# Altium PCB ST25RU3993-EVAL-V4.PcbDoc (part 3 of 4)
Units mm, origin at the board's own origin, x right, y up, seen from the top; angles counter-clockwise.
Board outline 76.25 x 96.25 mm, 6 copper layers (Top Layer, RF GND, Power, GND, Routing, Bottom GND), stack 1.022 mm thick; 319 components, 214 nets, 994 pads, 1429 vias.
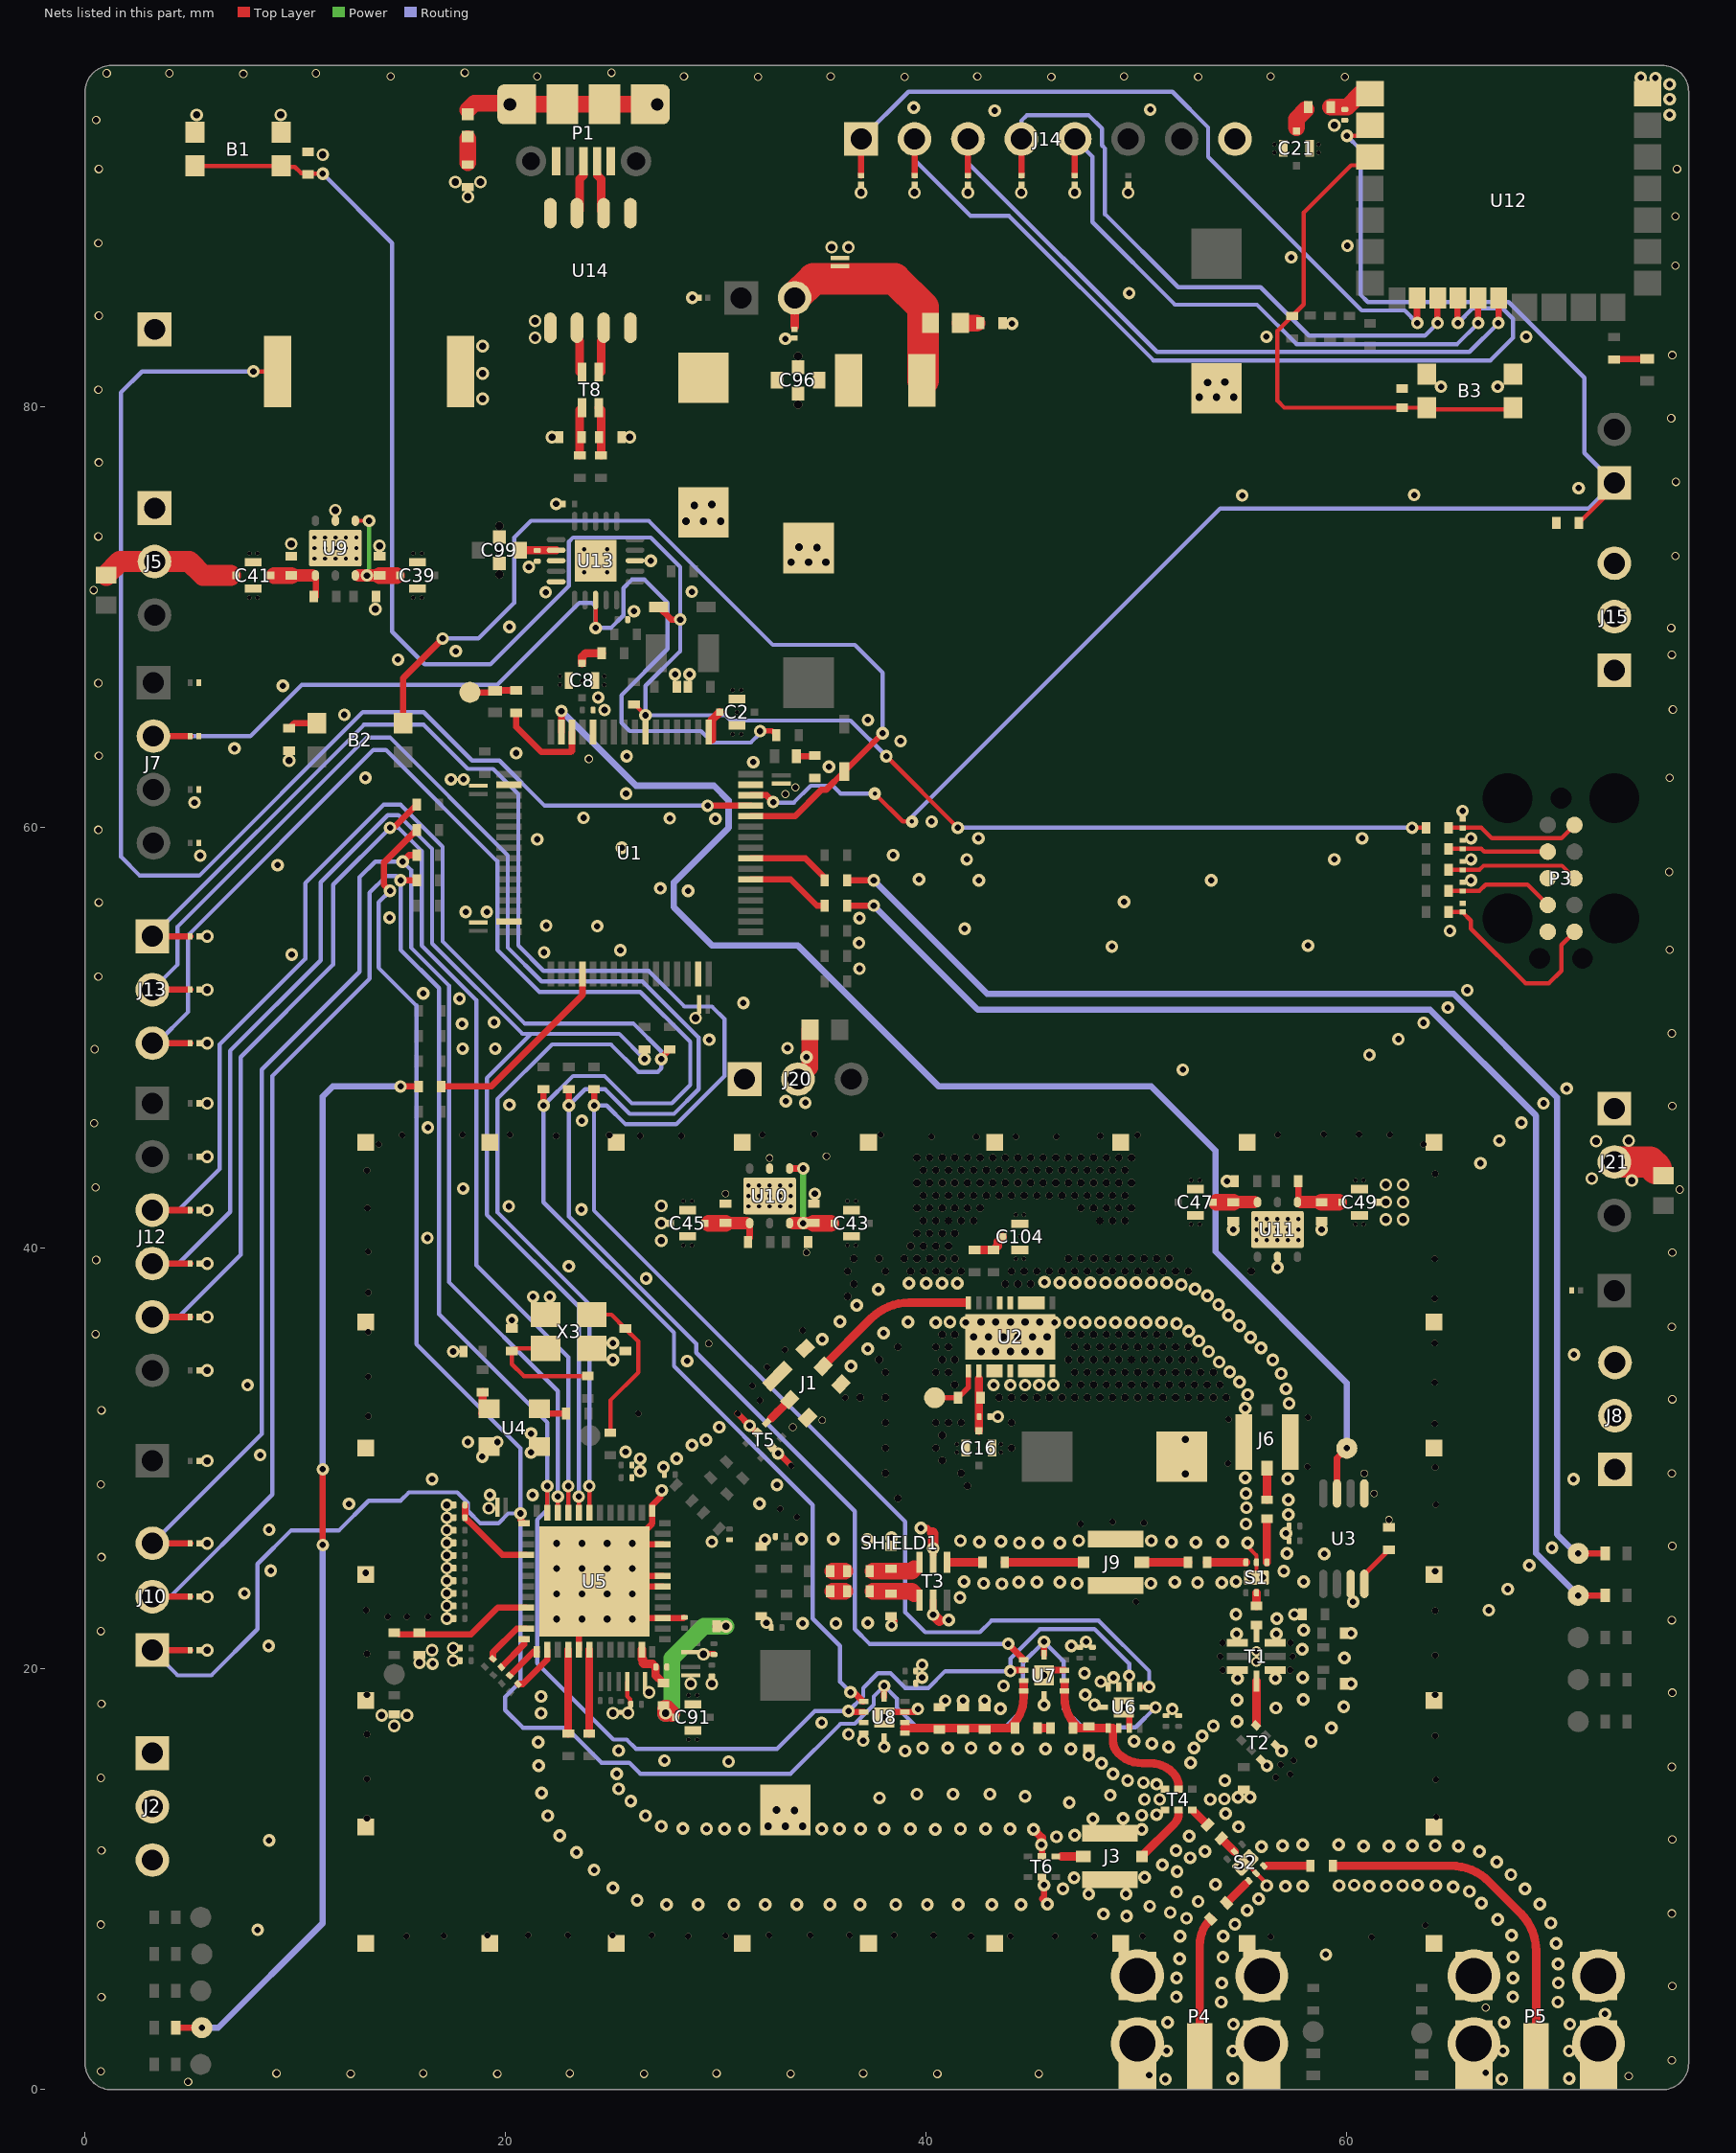
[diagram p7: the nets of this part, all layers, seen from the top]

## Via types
v1: diameter 0.6, hole 0.3, Top Layer to Bottom GND, tented both sides, 407 vias
v2: diameter 0.35, hole 0.35, Top Layer to Bottom GND, tented both sides, 245 vias
v3: diameter 0.61, hole 0.3, Top Layer to Bottom GND, tented both sides, 240 vias
v4: diameter 0.3, hole 0.3, Top Layer to Bottom GND, tented both sides, 105 vias
v5: diameter 0.4, hole 0.3, Top Layer to Bottom GND, tented both sides, 93 vias
v6: diameter 0.6/0.6/0.6/0.6/0.6/0.6 (per signal layer), hole 0.35, Top Layer to Bottom GND, tented both sides, 92 vias
v7: diameter 0.6, hole 0.35, Top Layer to Bottom GND, tented both sides, 71 vias
v8: diameter 0.2, hole 0.2, Top Layer to Bottom GND, tented both sides, 60 vias
v9: diameter 0.4, hole 0.2, Top Layer to Bottom GND, 45 vias
v10: diameter 0.6, hole 0.35, Top Layer to Bottom GND, 16 vias
v11: diameter 0.66, hole 0.33, Top Layer to Bottom GND, tented both sides, 16 vias
v12: diameter 0.35, hole 0.3, Top Layer to Bottom GND, tented both sides, 10 vias
v13: diameter 0.4, hole 0.4, Top Layer to Bottom GND, tented both sides, 6 vias
v14: diameter 1.8/2.51/2.51/2.51/2.51/2.51 (per signal layer), hole 1.71, Top Layer to Bottom GND, 6 vias
v15: diameter 0.5, hole 0.2, Top Layer to Bottom GND, 4 vias
v16: diameter 0.6, hole 0.3, Top Layer to Bottom GND, tented bottom, 4 vias
v17: diameter 0.5, hole 0.3, Top Layer to Bottom GND, tented both sides, 2 vias
v18: diameter 1.8/1.8/1.8/1.8/1.8/2.51 (per signal layer), hole 1.71, Top Layer to Bottom GND, 2 vias
v19: diameter 0.6, hole 0.2, Top Layer to Bottom GND, tented both sides, 2 vias
v20: diameter 0.4, hole 0.2, Top Layer to Bottom GND, tented both sides, 2 vias
v21: diameter 0.8, hole 0.4, Top Layer to Bottom GND, tented both sides, 1 vias

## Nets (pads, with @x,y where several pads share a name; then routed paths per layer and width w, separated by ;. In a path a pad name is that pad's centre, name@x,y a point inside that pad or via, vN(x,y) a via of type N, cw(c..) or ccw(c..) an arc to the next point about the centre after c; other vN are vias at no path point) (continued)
CD2: C59.1 C60.1 U5.40 | length 4.2
  Top Layer w0.3: C59.1@18.07,27.8 18.07,27.2 18.255,27.015 18.262,27.015 18.445,26.832 18.445,26.825 19.845,25.425 U5.40@20.975,25.425
CLK: D22.1 J10.1 R8.1 U5.37 U6.5 U7.5 U8.5 | length 116.3
  Top Layer w0.2: U6.5@50.375,18.175 v1(50.9,18.175)
  Top Layer w0.3: J10.1@3.2,20.9 D22.1@4.994,20.9 ; v1(14.5,57) 14.2,57.3 14.2,58.333 R8.1@15.767,59.9 ; v1(20.7,27.4) 20.7,27.1 U5.37@20.875,26.925 ; U8.5@38,18.675 v1(38,19.2) ; U7.5@45.6,20.675 v1(45.6,21.3)
  Routing w0.2: J10.1@3.2,20.9 4.4,19.7 6,19.7 8.2,21.9 8.2,25 9.8,26.6 12.075,26.6 13.475,28 15,28 15.4,28.4 17.7,28.4 18.2,27.9 18.2,27.525 18.8,26.925 19.65,26.925 20.125,27.4 v1(20.7,27.4) ; J10.1@3.2,21.1 J10.1@3.4,20.9 ; v1(14.5,57) 13.95,56.45 13.95,53.35 15.75,51.55 15.75,35.45 20.7,30.5 v1(20.7,27.4) ; v1(50.9,18.175) 49.95,17.225 47.425,17.225 46.525,18.125 46.525,20.375 v1(45.6,21.3) 44.6,20.3 44.6,18.075 43.75,17.225 39.55,17.225 38.6,18.175 38.6,18.6 v1(38,19.2) 37.5,18.7 37.5,18.3 36.6,17.4 35.925,17.4 33.55,15.025 26.4,15.025 25.875,15.55 24.55,15.55 22.888,17.213 20.812,17.213 19.975,18.05 19.975,18.675 20.7,19.4 v1(20.7,27.4)
COMN_A: C80.1 U5.48 | length 1.8
  Top Layer w0.3: C80.1@19.791,20.091 20.875,21.175 U5.48@20.875,21.425
COMN_B: C82.1 U5.2 | length 2.3
  Top Layer w0.3: C82.1@20.591,19.291 20.816,19.291 21.975,20.45 U5.2@21.975,20.925
COMP_A: C79.1 U5.47 | length 2.4
  Top Layer w0.3: C79.1@19.391,20.491 19.391,20.791 20.525,21.925 U5.47@20.975,21.925
COMP_B: C81.1 U5.1 | length 1.8
  Top Layer w0.3: C81.1@20.191,19.691 21.325,20.825 U5.1@21.475,20.825
CRC_ERR: D13.2 R66.2 TP17.1 | length 53.1
  Top Layer w0.3: D13.2@4.32,2.95 v1(5.55,2.95) ; v1(11.3,25.9) v1(11.3,29.5) ; v1(15,47.7) R66.2@15.867,47.7
  Routing w0.3: v1(5.55,2.95) 6.325,2.95 11.3,7.925 v1(11.3,25.9) ; v1(11.3,29.5) 11.3,47.225 11.775,47.7 v1(15,47.7)
CRC_ERR_LED: R66.1 U1.36 | length 9.5
  Top Layer w0.3: R66.1@16.933,47.7 19.3,47.7 23.65,52.05 U1.36@23.65,53.05
D_CMC_N: C101.1 R41.1 T8.3 | length 2.3
  Top Layer w0.41: T8.3@24.425,79.975 24.53,79.87 R41.1@24.53,77.708
D_CMC_P: C102.1 R47.1 T8.2 | length 2.3
  Top Layer w0.41: R47.1@23.52,77.708 23.52,78.575 23.52,78.825 23.52,79.075 23.52,79.87 T8.2@23.625,79.975
D_CON_N: P1.2 U14.2 | length 2
  Top Layer w0.41: P1.2@24.35,91.05 24.35,91.025 24.53,90.845 24.53,89.355 U14.2@24.66,89.225
D_CON_P: P1.3 U14.3 | length 2
  Top Layer w0.41: U14.3@23.39,89.225 23.52,89.355 23.52,90.845 23.7,91.025 P1.3@23.7,91.05
D_ESD_N: T8.4 U14.7 | length 1.7
  Top Layer w0.41: T8.4@24.53,81.675 24.53,83.145 U14.7@24.66,83.275
D_ESD_P: T8.1 U14.6 | length 1.7
  Top Layer w0.41: U14.6@23.39,83.275 23.52,83.145 T8.1@23.52,81.675
Detector: TP4.1 U1.15 U3.7 | length 66.5
  Top Layer w0.3: U1.15@22.65,64.55 v1(22.65,65.55) ; U3.7@59.529,28.35 59.529,30.029 v1(60,30.5)
  Routing w0.3: v1(22.65,65.55) 26.2,62 29.9,62 30.6,61.3 30.6,60 28,57.4 28,56.222 29.822,54.4 33.9,54.4 40.6,47.7 50.7,47.7 53.75,44.65 53.75,39.85 60,33.6 v1(60,30.5)
DTR: D48.1 J7.2 R37.1 U13.18 | length 48.2
  Top Layer w0.2: v1(24.275,69.5) U13.18@24.275,70.825
  Top Layer w0.25: v1(32.1,64.6) 32.667,64.6 R37.1@32.867,64.4
  Top Layer w0.3: J7.2@3.251,64.36 D48.1@4.994,64.36
  Routing w0.2: J7.2@3.251,64.36 7.86,64.36 10.3,66.8 19.6,66.8 23.5,70.7 24.1,70.7 24.275,70.525 v1(24.275,69.5) 25,69.5 25.6,70.1 25.6,71.4 26,71.8 26.6,71.8 27.7,70.7 27.7,68.5 25.5,66.3 25.5,65 25.9,64.6 29.294,64.6 29.844,64.05 31.65,64.05 32.1,64.5 v1(32.1,64.6)
EN: D35.1 J12.3 R13.1 U5.31 | length 79.7
  Top Layer w0.2: U5.31@23.975,27.425 v1(23.975,28.7)
  Top Layer w0.3: J12.3@3.2,41.82 D35.1@4.994,41.82 ; v1(27.4,49) 27.4,49.067 R13.1@27.8,49.467
  Routing w0.2: J12.3@3.2,41.82 4.44,41.82 6.4,43.78 6.4,49.7 10.475,53.775 10.475,57.375 14.2,61.1 15,61.1 17,59.1 17,54.6 20.9,50.7 26.067,50.7 27.4,49.367 v1(27.4,49) 27.4,48.567 27.233,48.4 26.3,48.4 25,49.7 22.2,49.7 19.6,47.1 19.6,41.725 23.975,37.35 v1(23.975,28.7) v1@23.975,28.5
ETC_1: D25.1 J13.1 R40.2 U6.6 | length 98.8
  Top Layer w0.2: U6.6@50.15,19.15 v1(50.6,19.15)
  Top Layer w0.3: J13.1@3.2,54.84 D25.1@4.994,54.84 ; v1(24.2,46.8) R40.2@24.2,47.567
  Routing w0.2: J13.1@3.2,54.84 13.26,64.9 16.1,64.9 18.2,62.8 19.4,62.8 20.6,61.6 20.6,54.4 21.8,53.2 26.8,53.2 28.5,51.5 29.807,51.5 30.4,50.907 30.4,48.2 28.1,45.9 25.7,45.9 24.8,46.8 v1(24.2,46.8) 24.2,41.8 39,27 39,22.7 39.95,21.75 42.55,21.75 43.1,22.3 48.2,22.3 50.6,19.9 v1(50.6,19.15)
ETC_2: D26.1 J13.2 R39.2 U7.6 | length 92.1
  Top Layer w0.3: J13.2@3.2,52.3 D26.1@4.994,52.3 ; v1(23,46.8) R39.2@23,47.567 ; v1(43.9,21.2) 43.9,21.175 U7.6@44.625,20.45
  Routing w0.2: J13.2@3.2,52.3 4.4,53.5 4.4,55.3 13.4,64.3 14.493,64.3 20.1,58.693 20.1,54.3 21.7,52.7 26.5,52.7 29.175,50.025 29.175,47.575 28,46.4 25.9,46.4 24.725,47.575 23.775,47.575 v1(23,46.8) 23,41.525 29.062,35.462 29.062,35.038 36.6,27.5 36.6,21.9 37.3,21.2 v1(43.9,21.2)
ETC_3: D27.1 J13.3 R38.2 U8.6 | length 89.5
  Top Layer w0.3: J13.3@3.2,49.76 D27.1@4.994,49.76 ; v1(21.8,46.8) R38.2@21.8,47.567 ; v1(36.4,18.9) 36.55,18.9 U8.6@37,18.45
  Routing w0.2: J13.3@3.2,49.76 3.41,49.76 4.9,51.25 4.9,54.9 13.7,63.7 14.307,63.7 19.6,58.407 19.6,54.2 21.6,52.2 26.4,52.2 28.775,49.825 28.775,47.775 27.9,46.9 26,46.9 24.7,48.2 23.2,48.2 v1(21.8,46.8) 21.8,42.2 28,36 28,34.4 34.6,27.8 34.6,22.4 35.9,21.1 35.9,19.4 v1(36.4,18.9)
EXT_PA_BIAS: R21.2 TP3.1 U2.1 | length 2.6
  Top Layer w0.25: TP3.1@40.4,32.9 R21.2@41.512,32.9 42,33.388 U2.1@42,34.18
extPA: D4.2 R18.2 TP11.1 | length 61.4
  Top Layer w0.3: R18.2@36.233,57.5 v1(37.5,57.5) ; v1(71,25.5) D4.2@72.28,25.5
  Routing w0.3: v1(37.5,57.5) 42.9,52.1 65.075,52.1 70,47.175 70,26.4 v1@70.9,25.5
extPA_LED: R18.1 U1.56 | length 4
  Top Layer w0.3: U1.56@31.65,58.55 34.25,58.55 35.167,57.633 R18.1@35.167,57.5
GND: B1.2 B1.3 B3.2 B3.3 BZ1.2 C1.2 C2.2 C3.2 C6.2 C7.1 C8.2 C9.2 C10.2 C11.2 C12.2 C13.2 C14.1 C15.2 C16.2 C17.1 C18.2 C19.2 C20.2 C21.2 C22.2 C23.2 C24.2 C25.2 C26.2 C27.2 C28.2 C29.2 C30.2 C31.2 C33.2 C34.2 C38.2 C39.2 C40.2 C41.2 C42.2 C43.2 C44.2 C45.2 C46.2 C47.2 C48.2 C49.2 C50.2 C52.1 C53.2 C55.2 C56.2 C57.1 C58.2 C59.2 C60.2 C61.2 C62.2 C63.2 C64.2 C66.2 C67.2 C68.2 C69.2 C70.2 C71.2 C72.2 C73.2 C74.2 C75.2 C76.2 C77.2 C78.2 C85.2 C86.2 C87.2 C88.2 C89.2 C90.2 C91.2 C92.2 C95.2 C96.2 C98.2 C99.2 C101.2 C102.2 C103.2 C104.2 C105.2 C106.2 C110.2 C111.2 D20.2 D21.2 D22.2 D23.2 D24.2 D25.2 D26.2 D27.2 D28.2 D29.2 D30.2 D31.2 D32.2 D33.2 D34.2 D35.2 D36.2 D37.2 D38.2 D39.2 D40.2 D41.2 D42.2 D43.2 D44.2 D45.2 D47.2 D48.2 D49.2 D50.2 D52.2 J1.G1 J1.G2 J2.1 J2.2 J2.3 J3.G1 J3.G2 J5.1 J6.G1 J6.G2 J8.1 J8.2 J8.3 J9.G1 J9.G2 J14.8 J15.1 J15.2 J15.3 J16.1 J20.1 J21.1 L11.1 L12.1 P3.3 P3.5 P4.2 P4.3 P4.4 P4.5 P5.2 P5.3 P5.4 P5.5 R16.1 R22.1 R23.1 R25.1 R26.1 R27.1 R29.1 R31.1 R35.1 R45.1 R78.1 R81.1 R86.1 R89.2 S1.5 S1.7 S2.5 S2.7 SHIELD1.1 SHIELD1.2 SHIELD1.3 SHIELD1.4 SHIELD1.5 SHIELD1.6 SHIELD1.7 SHIELD1.8 SHIELD1.9 SHIELD1.10 SHIELD1.11 SHIELD1.12 SHIELD1.13 SHIELD1.14 SHIELD1.15 SHIELD1.16 SHIELD1.17 SHIELD1.18 SHIELD1.19 SHIELD1.20 SHIELD1.21 SHIELD1.22 SHIELD1.23 SHIELD1.24 SHIELD1.25 SHIELD1.26 SHIELD1.27 SHIELD1.28 T1.1 T1.3 T1.5 T1.7 T2.3 T2.4 T3.2 T3.5 T4.3 T4.4 T5.2 T5.5 T6.2 T6.5 U1.12 U1.18 U1.31 U1.47 U1.63 U2.3 U2.4 U2.5 U2.6 U2.8 U2.9 U2.10 U2.14 U3.3 U3.5 U4.1 U4.2 U5.5 U5.15 U5.18 U5.19 U5.22 U5.25 U5.49 U6.3 U6.8 U6.9 U6.10 U7.3 U7.10 U8.3 U8.8 U8.9 U8.10 U9.0 U9.2 U10.0 U10.2 U11.0 U11.2 U12.7 U13.3 U13.13 U13.15 U13.21 U14.5 X3.2 X3.4 | length 39.6
  Top Layer w0.2: v6(25.1,17.9) 25.13,17.93 C89.2@25.475,17.93 ; C88.2@25.775,19.4 25.775,18.706 25.921,18.561 25.921,18.334 25.93,18.325 25.93,18.03 v6(25.814,17.914) ; S2.7@55.175,10.8 S2.5@55.688,10.287 56.2,9.775 v3(56.2,9.7) ; v3(55.275,26) 55.275,25.825 55.7,25.4 S1.5@55.7,25.075 S1.7@55.7,24.35
  Top Layer w0.25: v6(29.4,20.7) 29.43,20.73 C66.2@29.9,20.73
  Top Layer w0.3: U5.5@23.475,20.925 23.475,24.175 U5.49@24.225,24.175 ; U5.49@24.825,23.925 U5.18@27.475,23.925 ; U5.49@24.825,24.425 U5.19@27.475,24.425 ; 27.34,28.165 26.975,27.8 U5.25@26.975,27.525 26.975,26.925 v11(26.025,25.975) U5.49@25.975,25.925 ; U5.22@27.475,25.925 U5.49@25.975,25.925 ; C90.2@28.477,22.447 28.455,22.425 U5.15@27.475,22.425 25.975,22.425 U5.49@24.225,24.175 ; v4(31.05,32.15) 31.025,32.15 v1(31.6,31.575) ; v1@31.725,31.45 31.925,31.25 T5.2@31.95,31.25 ; C1.2@32.15,22.517 32.15,22.5 C1.2@32.275,22.375 ; C3.2@32.15,25.833 32.15,25.975 v1(32.325,26.15) ; T5.5@32.65,30.55 v1@32.875,30.325 ; v1(32.95,30.25) 33,30.25 v4(33.575,29.675) ; v1(38,17.7) 38.25,17.95 U8.3@38.975,17.95 39.45,17.95 v1(39.6,18.1) ; C6.2@38.325,22.514 38.325,22.45 v1@38.5,22.275 ; C7.1@38.325,25.831 38.225,25.931 38.35,26.056 v1(38.35,26.25) ; v3(39.75,26.7) v3@40.054,26.7 ; v1(40.325,22.588) T3.5@40.325,23.275 ; T3.2@40.325,25.425 v1(40.325,25.743) ; v1@45.5,9.787 T6.5@45.5,10.105 ; T6.2@45.5,11.095 v1@45.5,11.4 ; v1(45.6,19.7) 45.85,19.95 U7.3@46.575,19.95 ; v1(45.602,9.725) 45.602,9.177 45.5,9.075 v3(45.75,8.825) ; v1(49.4,18.175) 49.65,17.925 U6.3@49.65,17.2 ; U5.49@24.225,24.175 v11(24.825,24.775) U5.49@25.975,25.925
  Top Layer w0.4: v3(45.1,12.375) 45.5,11.975 45.475,11.95 v1(45.475,11.65)
  Top Layer w0.5: 40.281,26.497 cw(c40.173,26.389) 40.325,26.389 v1(40.325,25.743) ; v1(40.325,22.588) 40.618,22.294
  other v1: 51.371,0.498 67.371,0.498 54.574,0.535 70.574,0.535 51.429,1.848 54.574,1.841 67.429,1.848 70.574,1.841 54.603,3.11 70.603,3.11 51.473,3.198 67.473,3.198 72.275,3.6 54.029,4.166 70.029,4.166 51.893,4.413 67.893,4.413 54.054,5.07 70.054,5.07 51.902,5.316 67.902,5.316 54.1,6.3 67.9,6.3 59,6.425 8.2,7.6 49.525,8.25 48.425,8.35 51.6,8.425 50.625,8.725 47.725,9.3 49.5,9.3 51.9,9.4 51.925,10.375 54.963,10.588 55.387,11.012 52.55,11.025 8.75,11.85 50.25,12.375 47.925,12.875 50.25,13.05 50.95,13.075 46.8,13.65 50.375,13.8 51.1,13.8 53.5,13.8 54.175,13.825 37.775,13.875 54.825,13.9 55.4,13.9 44.7,13.95 48.75,14 39.55,14.05 41.275,14.05 43.025,14.05 50.95,14.525 50.325,14.6 56.2,15.4 30.6,15.6 27.55,15.65 47.725,15.9 56.9,16.1 38,16.3 37,16.6 36.3,16.9 35.025,17.45 51.7,18.1 45.6,18.3 48,18.3 40.9,18.5 41.75,18.5 42.775,18.5 60.2,19.3 48.3,19.4 39.8,19.6 48.9,19.6 39.8,20.2 16.525,20.25 8.725,21.1 46.9,21.1 47.6,21.3 60.2,21.7 38.35,22.075 32.4,22.2 57.5,22.6 66.75,22.8 60.3,23.2 7.575,23.6 67.65,23.8 55.4,24.35 56,24.35 8.825,24.675 68.675,24.925 57.15,25.5 69.75,25.775 29.8,26.05 8.75,26.625 12.55,27.85 19.25,28.275 21.275,28.275 27.425,28.5 16.5,29.025 70.775,29.025 26.4,29.4 27.5,29.6 26.4,30 18.885,30.1 8.325,30.175 21.2,30.3 25.7,30.325 18.2,30.794 19.6,30.794 21.2,31.2 43.4,32 7.725,33.5 43.2,33.5 44,33.5 44.7,33.5 45.375,33.5 46.05,33.5 28.625,34.65 25.1,34.7 70.8,34.95 17.5,35.1 25.1,35.5 20.3,36.6 21.3,37.7 22.1,37.7 26.675,38.575 56.7,39.1 23,39.15 16.275,40.5 54.6,40.9 58.8,40.9 23.6,41.85 20.15,42 34.7,42.6 17.975,42.85 54.3,43.2 66.35,44.05 67.25,45.125 16.3,45.75 68.3,45.975 23.625,46.075 20.175,46.825 69.35,46.9 70.45,47.6 52.2,48.5 61.075,49.2 17.95,49.5 19.5,49.5 33.4,49.525 29.675,49.925 62.45,49.95 17.925,50.675 63.65,50.725 19.45,50.75 64.8,51.45 31.3,51.675 17.8,51.875 16.075,52.125 65.725,52.275 36.825,53.3 9.825,53.975 21.825,54.075 25.45,54.175 48.825,54.35 58.15,54.4 36.8,54.525 64.9,55.1 41.825,55.2 24.35,55.325 21.925,55.35 36.825,55.7 14.475,55.725 18.1,56 19.1,56 49.4,56.475 28.675,57 27.35,57.125 42.5,57.5 53.55,57.5 65.9,57.5 39.65,57.55 9.15,58.225 41.925,58.5 59.4,58.5 65.9,58.5 5.475,58.675 38.425,58.7 25.525,59.05 21.5,59.45 42.475,59.5 60.725,59.5 65.9,59.5 40.25,60.3 29.975,60.425 27.8,60.45 23.7,60.475 65.5,60.8 5.2,61.2 25.725,61.625 17.4,62.3 18,62.3 13.325,62.375 35.375,62.9 31.775,63.125 25.75,63.4 20.5,63.55 7.1,63.775 38.775,64.125 37.225,65.125 12.325,65.375 24.7,65.6 24.4,66.2 9.4,66.75 28.054,67.3 28.746,67.3 14.875,68 17.625,68.4 20.175,69.55 26.1,70.3 21.9,71.2 28.85,71.225 21.1,72.4 26.9,72.7 22.4,75.4 55.025,75.8 63.2,75.825 71.025,76.15 64.475,80.975 67.175,80.975 33.3,83.25 56.175,83.35 68.525,83.35 44.075,83.975 28.875,85.2 49.65,85.425 57.35,87.125 60.025,87.675 75.35,93.9 43.25,94.1 50.65,94.15 39.4,94.25 75.35,94.65 75.35,95.35 74.675,95.65 73.975,95.675
  other v2: 38.655,28.115 41.955,28.715 52.325,29.275 38.055,29.315 41.655,29.315 40.755,29.915 38.055,30.515 40.455,30.515 44.055,30.515 52.325,30.925 40.755,31.115 38.055,31.715 40.455,31.715 41.055,31.715 41.655,31.715 44.055,31.715 36.855,32.915 38.055,32.915 43.455,32.915 44.055,32.915 44.655,32.915 45.255,32.915 45.855,32.915 46.455,32.915 47.055,32.915 47.655,32.915 48.255,32.915 48.855,32.915 49.455,32.915 50.055,32.915 50.655,32.915 51.255,32.915 51.855,32.915 52.455,32.915 53.055,32.915 53.655,32.915 54.255,32.915 41.355,33.515 46.755,33.515 47.355,33.515 47.955,33.515 48.555,33.515 49.155,33.515 49.755,33.515 50.355,33.515 50.955,33.515 51.555,33.515 52.155,33.515 52.755,33.515 53.355,33.515 53.955,33.515 38.055,34.115 40.455,34.115 41.055,34.115 47.055,34.115 47.655,34.115 48.255,34.115 48.855,34.115 49.455,34.115 50.055,34.115 50.655,34.115 51.255,34.115 51.855,34.115 52.455,34.115 53.055,34.115 53.655,34.115 37.755,34.715 40.755,34.715 41.355,34.715 46.755,34.715 47.355,34.715 47.955,34.715 48.555,34.715 49.155,34.715 49.755,34.715 50.355,34.715 50.955,34.715 51.555,34.715 52.155,34.715 52.755,34.715 38.655,35.315 40.455,35.315 41.055,35.315 47.055,35.315 47.655,35.315 48.255,35.315 48.855,35.315 49.455,35.315 50.055,35.315 50.655,35.315 51.255,35.315 51.855,35.315 52.455,35.315 40.755,35.915 41.355,35.915 46.755,35.915 47.355,35.915 47.955,35.915 48.555,35.915 49.155,35.915 49.755,35.915 50.355,35.915 50.955,35.915 51.555,35.915 36.255,37.715 36.555,38.315 43.755,38.315 44.355,38.315 44.955,38.315 36.255,38.915 38.055,38.915 39.255,38.915 39.855,38.915 40.455,38.915 41.055,38.915 41.655,38.915 44.055,38.915 44.655,38.915 45.255,38.915 45.855,38.915 46.455,38.915 47.055,38.915 47.655,38.915 48.255,38.915 48.855,38.915 49.455,38.915 50.055,38.915 50.655,38.915 51.255,38.915 51.855,38.915 52.455,38.915 55.455,38.915 36.555,39.515 37.755,39.515 38.955,39.515 39.555,39.515 40.155,39.515 40.755,39.515 41.355,39.515 46.755,39.515 47.355,39.515 47.955,39.515 48.555,39.515 49.155,39.515 49.755,39.515 50.355,39.515 50.955,39.515 51.555,39.515 39.255,40.115 39.855,40.115 40.455,40.115 41.055,40.115 39.555,40.715 40.155,40.715 40.755,40.715 41.355,40.715 39.855,41.315 40.455,41.315 41.055,41.315 41.655,41.315 42.255,41.315 48.255,41.315 48.855,41.315 49.455,41.315 39.555,41.915 40.155,41.915 40.755,41.915 41.355,41.915 41.955,41.915 42.555,41.915 47.355,41.915 47.955,41.915 48.555,41.915 49.155,41.915 49.755,41.915 39.855,42.515 40.455,42.515 41.055,42.515 41.655,42.515 42.255,42.515 42.855,42.515 43.455,42.515 44.055,42.515 44.655,42.515 45.255,42.515 45.855,42.515 46.455,42.515 47.055,42.515 47.655,42.515 48.255,42.515 48.855,42.515 49.455,42.515 39.555,43.115 40.155,43.115 40.755,43.115 41.355,43.115 41.955,43.115 42.555,43.115 43.155,43.115 43.755,43.115 44.355,43.115 44.955,43.115 45.555,43.115 46.155,43.115 46.755,43.115 47.355,43.115 47.955,43.115 48.555,43.115 49.155,43.115 49.755,43.115 39.855,43.715 40.455,43.715 41.055,43.715 41.655,43.715 42.255,43.715 42.855,43.715 43.455,43.715 44.055,43.715 44.655,43.715 45.255,43.715 45.855,43.715 46.455,43.715 47.055,43.715 47.655,43.715 48.255,43.715 48.855,43.715 49.455,43.715 39.555,44.315 40.155,44.315 40.755,44.315 41.355,44.315 41.955,44.315 42.555,44.315 43.155,44.315 43.755,44.315 44.355,44.315 44.955,44.315 45.555,44.315 46.155,44.315 46.755,44.315 47.355,44.315 47.955,44.315 48.555,44.315 49.155,44.315 49.755,44.315
  other v3: 70.05,5.975 52.05,6.225 69.95,6.95 52.075,7.3 54.125,7.3 67.825,7.35 54.675,7.875 69.7,7.925 67.175,8.1 52.375,8.15 55.25,8.525 27.65,8.8 29.15,8.8 30.85,8.8 32.35,8.8 33.85,8.8 35.425,8.8 36.85,8.8 38.55,8.8 40.05,8.8 41.525,8.8 43.125,8.8 44.5,8.8 69.175,8.825 66.4,8.875 52.925,8.95 26.25,9 55.8,9.075 65.825,9.425 46.5,9.55 68.475,9.55 25.1,9.6 65.05,9.65 57.075,9.675 57.9,9.675 61.075,9.675 61.875,9.675 59.625,9.7 62.65,9.7 64.225,9.7 60.35,9.725 63.375,9.725 53.75,9.75 47.025,10.075 50.375,10.1 67.8,10.225 24.2,10.45 51.225,10.7 67.125,10.825 23.375,11.275 53.25,11.325 66.3,11.325 51.875,11.375 55.95,11.55 60.8,11.575 62,11.575 65.3,11.575 56.95,11.6 63.125,11.6 64.2,11.6 57.9,11.65 59.6,11.65 46.2,12.025 52.5,12.05 22.575,12.075 47.05,12.1 40.425,12.375 29.55,12.4 30.4,12.4 31.35,12.4 35.025,12.4 35.875,12.4 36.875,12.4 38,12.4 39.25,12.4 41.625,12.4 42.825,12.4 43.975,12.4 28.425,12.425 54.85,12.5 27.4,12.525 49.35,12.9 22,13.025 26.65,13.025 54.225,13.125 25.95,13.725 21.7,14.1 25.375,14.3 49.575,14.7 54.2,14.7 25.275,15.025 48.875,15.025 21.575,15.4 48.325,15.525 52.575,15.55 25.375,16.125 39,16.1 44.35,16.2 45.675,16.2 46.875,16.2 39.825,16.25 41.025,16.25 42.125,16.25 43.275,16.25 52.725,16.25 51.525,16.3 50.725,16.45 21.55,16.525 58.3,16.55 49.875,16.575 53.125,16.825 59.275,17.2 53.65,17.3 54.778,17.501 21.675,17.9 43.525,18.125 56.625,18.15 59.85,18.2 54.778,18.526 57.925,18.55 21.675,18.7 47.55,18.775 43.675,19.2 54.8,19.55 56.6,19.55 57.9,19.6 47.525,19.8 59.875,20.525 57.875,20.95 54.75,21.675 56.65,21.675 57.95,21.85 34.125,22.175 35.7,22.175 37.225,22.2 41.075,22.325 56.675,22.4 54.725,22.6 41.6,23.4 43.6,24.05 42.725,24.075 47.175,24.075 50.675,24.075 52.9,24.1 54.05,24.1 44.4,24.125 45.25,24.125 46.35,24.125 51.825,24.125 41.8,24.15 54.725,24.15 57.95,24.15 57,24.65 58.925,25.475 44.425,26 45.3,26 46.35,26 52.825,26.025 42.525,26.05 51.65,26.05 54.1,26.05 43.55,26.075 41.625,26.1 47.25,26.1 50.7,26.1 37.2,26.15 34.075,26.175 35.575,26.175 57.1,26.45 55.2,26.9 57.225,27.35 55.225,27.675 32.075,27.875 57.225,28.05 55.2,28.35 32.9,28.75 57.2,29.05 55.175,29.1 28.125,30 28.85,30.65 29.525,30.9 30.15,31.5 55.175,32.4 57.25,32.625 55.275,33.05 57.1,33.325 54.9,33.65 56.875,34.05 54.425,34.125 36.425,34.4 53.925,34.6 56.475,34.7 53.425,35.1 37.225,35.225 55.925,35.275 52.95,35.6 35.05,35.675 55.425,35.775 37.975,35.975 52.475,36.075 54.9,36.325 51.9,36.425 40.45,36.475 41.875,36.475 46.1,36.475 46.825,36.475 47.55,36.475 48.275,36.475 49,36.475 49.725,36.475 50.45,36.475 51.175,36.475 39.125,36.5 41.125,36.5 35.9,36.525 54.375,36.825 36.7,37.3 53.9,37.325 53.375,37.75 37.725,38.05 52.775,38.075 52.125,38.275 39.175,38.35 40,38.35 40.75,38.35 41.475,38.35 46.35,38.375 47.075,38.375 47.8,38.375 48.525,38.375 49.25,38.375 49.975,38.375 50.7,38.375 51.425,38.375 45.625,38.4
  other v4: 61.175,7.25 56.375,7.275 15.275,7.3 28.675,7.3 42.125,7.3 44,7.3 46.125,7.3 48,7.3 50.3,7.3 17.05,7.325 30.45,7.325 19.125,7.35 21.075,7.35 22.95,7.35 25.075,7.35 26.95,7.35 32.525,7.35 34.475,7.35 36.35,7.35 38.475,7.35 40.35,7.35 63.725,7.825 13.4,12.9 64.25,12.975 64.225,14.75 13.4,14.775 56.625,14.85 57.3,15 56.85,15.45 57.475,15.65 64.2,16.825 13.4,16.9 13.4,18.775 64.2,18.775 54.1,19.95 57.3,19.95 53.975,20.6 57.425,20.6 64.2,20.65 13.4,20.725 54.1,21.25 57.3,21.25 14.4,22.5 15.3,22.5 16.3,22.5 64.2,22.775 13.375,22.8 49.975,23.2 13.35,24.575 64.2,24.65 47.325,26.9 50.35,26.95 48.85,27 33.85,27.225 33.05,27.625 64.225,27.825 64.2,29.6 58.133,29.615 54.35,29.775 64.175,31.675 54.375,31.875 58.15,31.975 13.45,32.025 26.3,32.154 32.1,32.775 36.15,32.9 31.725,33.475 64.175,33.625 13.45,33.9 32.425,34.35 33.275,35.175 64.175,35.5 13.45,36.025 34.125,36.1 64.175,37.625 13.45,37.9 64.175,39.5 13.45,39.85 13.425,41.925 64.2,43.55 13.4,43.7 13.95,44.95 63.65,44.95 40.25,45.325 42.375,45.325 44.25,45.325 46.2,45.325 22.4,45.35 26.4,45.35 28.35,45.35 48.275,45.35 15.075,45.375 24.925,45.375 50.05,45.375 17.95,45.4 20.2,45.4 32.2,45.4 37.825,45.4 56.725,45.4 62.05,45.4 34.675,45.425 58.9,45.425 60.575,45.425
  other v5: 4.9,0.375 73.4,0.65 50.6,0.7 12.625,0.75 19.6,0.75 26.575,0.75 33.55,0.75 40.525,0.75 45.35,0.75 9.1,0.775 16.075,0.775 23.05,0.775 30.025,0.775 37,0.775 66.6,0.8 0.75,0.875 75.45,1.4 66.6,3.9 0.775,4.4 75.475,4.925 0.75,7.85 75.45,8.375 0.775,11.375 75.475,11.9 0.75,14.825 75.45,15.35 0.775,18.35 75.475,18.875 0.75,21.8 75.45,22.325 0.775,25.325 75.475,25.85 0.75,28.775 75.45,29.3 0.775,32.3 75.475,32.825 0.5,35.925 75.45,36.275 0.525,39.45 75.475,39.8 75.825,42.8 0.5,42.9 0.425,45.95 75.475,46.775 0.45,49.475 75.45,50.225 0.625,52.925 75.35,54.2 0.65,56.45 75.325,57.9 0.625,59.9 33.3,61.6 33.775,61.925 75.35,62.375 23.95,63.275 0.65,63.425 75.5,65.625 0.625,66.875 75.45,68.225 75.425,69.5 0.4,71.3 75.625,72.925 0.625,73.85 75.65,76.45 0.65,77.375 75.425,79.475 0.625,80.825 75.475,82.475 0.65,84.35 75.625,86.725 0.625,87.8 75.625,89.075 0.65,91.325 75.7,91.325 0.525,93.65 32,95.7 38.975,95.7 45.95,95.7 52.925,95.7 59.9,95.7 14.525,95.725 21.5,95.725 28.475,95.725 35.45,95.725 42.425,95.725 49.4,95.725 56.375,95.725 7.525,95.85 1.025,95.875 4,95.875 10.975,95.875 18.05,95.9 25.025,95.9
  other v6: 14.7,17.3 14.1,17.8 15.3,17.8 26.821,18.888 28.8,19.3 29.8,19.3 15.9,20.3 17.5,20.4 5.8,20.9 16.5,20.9 17.5,21 17.2,22.4 17.2,23 5.8,23.44 17.2,23.6 17.2,24.2 17.2,24.8 17.2,25.4 5.8,25.98 17.2,26 17.2,26.6 17.2,27.2 19.2,27.65 17.2,27.8 5.8,29.9 5.8,34.2 5.8,36.74 5.8,39.28 5.8,41.82 5.8,44.36 5.8,46.9 5.8,49.76 5.8,52.3 5.8,54.84 9.7,63.2 13.8,70.4 14,73.4 9.8,73.5 11.9,75.1 22.2,78.575 25.9,78.575 18.9,80.4 18.9,81.6 18.9,82.9 21.4,83.3 21.4,84.1 35.5,87.6 36.3,87.6 18.2,90 36.9,90.2 39.44,90.2 41.98,90.2 44.52,90.2 47.06,90.2 49.6,90.2 17.6,90.7 18.8,90.7 11.3,92 59.4,93.4 5.3,93.9 9.3,93.9
  other v7: 32.475,12.525 33.3,12.525 34.125,12.525 33.725,13.275 32.875,13.3 29.025,50.95 33.575,72.625 34.4,72.625 35.225,72.625 34.8,73.325 33.95,73.35 28.575,74.575 29.4,74.575 30.225,74.575 28.975,75.325 29.8,75.375 52.975,80.475 53.8,80.475 54.625,80.475 53.375,81.175 54.2,81.2
  other v8: 28.7,16.65 29.1,16.65 28.9,17.7 28.7,18.75 29.1,18.75 41.45,30.3 43.55,30.3 42.5,30.5 41.45,30.7 43.55,30.7 44.25,39.5 44.65,39.5 28.45,40.15 28.85,40.15 36.25,40.15 36.65,40.15 44.45,40.55 52.6,41.15 53,41.15 60.4,41.15 60.8,41.15 28.65,41.2 36.45,41.2 44.25,41.6 44.65,41.6 52.8,42.2 60.6,42.2 28.45,42.25 28.85,42.25 36.25,42.25 36.65,42.25 52.6,43.25 53,43.25 60.4,43.25 60.8,43.25 30.8,64.45 31.2,64.45 31,65.5 30.8,66.55 31.2,66.55 22.58,66.8 24.68,66.8 23.63,67 22.58,67.2 24.68,67.2 7.8,70.95 8.2,70.95 15.6,70.95 16,70.95 8,72 15.8,72 7.8,73.05 8.2,73.05 15.6,73.05 16,73.05 56.55,92.1 58.65,92.1 57.6,92.3 56.55,92.5 58.65,92.5
  other v9: 55.7,40.4 56.2,40.4 56.7,40.4 57.2,40.4 57.7,40.4 55.7,40.9 56.2,40.9 56.7,40.9 57.2,40.9 57.7,40.9 55.7,41.4 56.2,41.4 56.7,41.4 57.2,41.4 57.7,41.4 31.55,42 32.05,42 32.55,42 33.05,42 33.55,42 31.55,42.5 32.05,42.5 32.55,42.5 33.05,42.5 33.55,42.5 31.55,43 32.05,43 32.55,43 33.05,43 33.55,43 10.9,72.8 11.4,72.8 11.9,72.8 12.4,72.8 12.9,72.8 10.9,73.3 11.4,73.3 11.9,73.3 12.4,73.3 12.9,73.3 10.9,73.8 11.4,73.8 11.9,73.8 12.4,73.8 12.9,73.8
  other v10: 42.6,35.1 43.3,35.1 44,35.1 44.7,35.1 45.4,35.1 42.25,35.8 42.95,35.8 43.65,35.8 44.35,35.8 45.05,35.8 45.75,35.8 42.6,36.5 43.3,36.5 44,36.5 44.7,36.5 45.4,36.5
  other v11: 22.425,22.375 23.625,22.375 24.825,22.375 26.025,22.375 22.425,23.575 23.625,23.575 24.825,23.575 26.025,23.575 22.425,24.775 23.625,24.775 26.025,24.775 22.425,25.975 23.625,25.975 24.825,25.975
  other v12: 62,27.1 61.3,28.35 60.829,29.3 33.65,31.5 35.05,31.825 29.65,35.475 34.3,39.8 30.45,42.6 32.55,44.3 35.25,44.375
  other v13: 19.7,72.05 19.7,73.2 19.7,74.35 33.9,80.125 33.9,81.275 33.9,82.425
  other v14: 50.04,2.185 55.96,2.185 66.04,2.185 71.96,2.185 55.96,5.415 71.96,5.415
  other v15: 23.725,72.15 24.825,72.15 23.725,73.25 24.825,73.25
  other v17: 55.7,20.35 55.7,20.85
  other v18: 50.04,5.415 66.04,5.415
IN_N: C94.2 U5.6 | length 4
  Top Layer w0.37: C94.2@23.975,16.933 U5.6@23.975,20.925
IN_P: C93.2 U5.4 | length 4
  Top Layer w0.37: C93.2@22.975,16.933 22.975,17.155 U5.4@22.975,20.925
intPA: D2.2 R15.2 TP6.1 | length 61.8
  Top Layer w0.3: R15.2@36.233,56.3 v1(37.5,56.3) ; v1(71,23.5) D2.2@72.28,23.5
  Routing w0.3: v1(37.5,56.3) 42.45,51.35 63.95,51.35 69,46.3 69,25.5 v1(71,23.5)
intPA_LED: R15.1 U1.54 | length 4
  Top Layer w0.3: U1.54@31.65,57.55 33.55,57.55 34.8,56.3 R15.1@35.167,56.3
IRQ: D36.1 J12.4 R12.1 U5.32 | length 74.1
  Top Layer w0.2: U5.32@23.475,27.425 v1(23.475,28.2)
  Top Layer w0.3: J12.4@3.2,39.28 D36.1@4.994,39.28 ; v1(26.6,49) R12.1@26.6,49.467
  Routing w0.2: J12.4@3.2,39.28 4.44,39.28 6.9,41.74 6.9,49.4 11.2,53.7 11.2,57.407 14.393,60.6 14.9,60.6 16.5,59 16.5,54.5 20.8,50.2 21.2,50.2 ; v1@23.475,28.1 v1(23.475,28.2) 23.475,37.225 19.1,41.6 19.1,48.1 21.2,50.2 ; v1(26.6,49) 25.4,50.2 21.2,50.2
JTCK: D39.1 J14.3 U12.24 | length 33.6
  Top Layer w0.3: D39.1@41.98,91.006 J14.3@41.98,92.75 ; v1(67.2,84) 67.21,84.01 U12.24@67.21,85.2
  Routing w0.2: J14.3@41.98,92.75 41.98,91.62 50.975,82.625 65.825,82.625 v1(67.2,84)
JTDI: D40.1 J14.5 U12.23 | length 28.4
  Top Layer w0.3: D40.1@47.06,91.006 J14.5@47.06,92.75 ; U12.23@66.23,85.2 66.23,84.015 v1(66.245,84)
  Routing w0.2: J14.5@47.06,92.75 47.9,91.91 47.9,88.8 51.825,84.875 55.725,84.875 57.6,83 65.245,83 v1(66.245,84)
JTDO: D41.1 J14.2 U12.22 | length 40.8
  Top Layer w0.3: D41.1@39.44,91.006 J14.2@39.44,92.75 ; U12.22@65.265,85.2 65.265,84.015 v1(65.28,84)
  Routing w0.2: J14.2@39.44,92.75 39.44,91.76 42.105,89.095 43.93,89.095 50.8,82.225 66.825,82.225 67.9,83.3 67.9,84.2 67.4,84.7 65.98,84.7 v1(65.28,84)
JTMS: D42.1 J14.4 U12.21 | length 30.6
  Top Layer w0.3: D42.1@44.52,91.006 J14.4@44.52,92.75 ; U12.21@64.3,85.2 64.3,84.015 v1(64.315,84)
  Routing w0.2: J14.4@44.52,92.75 44.52,93.62 44.775,93.875 47.725,93.875 48.35,93.25 48.35,92.45 48.5,92.3 48.5,89.175 51.975,85.7 55.9,85.7 58.2,83.4 63.715,83.4 v1(64.315,84)
JTRST: D43.1 J14.1 U12.20 | length 35.7
  Top Layer w0.3: D43.1@36.9,91.006 J14.1@36.9,92.75 ; U12.20@63.335,85.2 63.335,84.015 v1(63.35,84)
  Routing w0.2: J14.1@36.9,92.75 39.15,95 51.7,95 53.4,93.3 53.4,91.9 60.7,84.6 62.75,84.6 v1(63.35,84)
LF_CEXT: C56.1 R33.2 U5.45 | length 6.6
  Top Layer w0.3: R33.2@14.933,21.654 18.354,21.654 19.625,22.925 U5.45@20.975,22.925
LP_Filter_IN: C109.2 T1.8
LP_Filter_OUT: T1.4 T2.6 | length 2
  Top Layer w0.4: T2.6@55.7,17.4 T1.4@55.7,19.425
MCU: D1.2 R14.2 TP5.1 | length 2.2
  Top Layer w0.3: TP5.1@18.3,66.441 19.421,66.441 D1.2@19.5,66.52 19.513,66.533 R14.2@20.5,66.533
MCU_LED: R14.1 U1.14 | length 4.7
  Top Layer w0.3: R14.1@20.5,65.467 20.5,64.8 21.7,63.6 23.1,63.6 23.15,63.65 U1.14@23.15,64.55
MISO: D24.1 J10.3 R9.1 U5.34 | length 74.8
  Top Layer w0.2: U5.34@22.475,27.425 v1(22.475,28.2)
  Top Layer w0.3: J10.3@3.2,25.98 D24.1@4.994,25.98 ; v1(15.1,58.394) 15.406,58.7 R9.1@15.767,58.7
  Routing w0.2: J10.3@3.2,25.98 8.4,31.18 8.4,48.5 13.05,53.15 13.05,57.65 13.794,58.394 v1(15.1,58.394) 15.5,57.994 15.5,54.3 17.3,52.5 17.3,38.4 22.475,33.225 v1(22.475,28.2) v1@22.475,28.1
MOSI: D23.1 J10.2 R11.1 U5.35 U6.7 U7.7 U8.7 | length 120.8
  Top Layer w0.2: U5.35@21.975,27.425 v1(21.975,28.7) ; U6.7@49.65,19.075 U6.7@49.65,19.15 v1@49.65,19.6
  Top Layer w0.3: J10.2@3.2,23.44 D23.1@4.994,23.44 ; v1(15,57.5) R11.1@15.767,57.5 ; v1(36.3,18) 36.35,17.95 U8.7@37.025,17.95 ; v1(44,19.9) 44.05,19.95 U7.7@44.625,19.95
  Routing w0.2: J10.2@3.2,23.44 4.04,23.44 8.9,28.3 8.9,48.2 13.525,52.825 13.525,56.919 14.306,57.7 14.8,57.7 v1(15,57.5) 15,54.2 16.825,52.375 16.825,36.875 21.975,31.725 v1(21.975,28.7) 21.975,27.575 21.5,27.1 21.5,20.275 25.125,16.65 25.75,16.65 26.2,16.2 32.9,16.2 34.7,18 v1(36.3,18) 37,18.7 37,19.1 37.7,19.8 38.3,19.8 39,19.1 40.1,19.1 40.9,19.9 v1(44,19.9) 44,20.5 45.4,21.9 48,21.9 49.65,20.25 v1(49.65,19.675)
NCS: D37.1 J12.5 R7.1 U5.33 | length 68.7
  Top Layer w0.2: U5.33@22.975,27.425 v1(22.975,28.7)
  Top Layer w0.3: J12.5@3.2,36.74 D37.1@4.994,36.74 ; v1(14.5,60) 14.667,60 R7.1@15.767,61.1
  Routing w0.2: J12.5@3.2,36.74 4.44,36.74 7.4,39.7 7.4,49.1 11.8,53.5 11.8,57.3 v1(14.5,60) 14.9,60 16,58.9 16,54.4 18.6,51.8 18.6,39.2 22.975,34.825 v1(22.975,28.7) v1@22.975,28.5
NetB1_1: B1.1 B1.4 C25.1 D9.1 R5.2 R61.2 U1.7 | length 97.9
  Top Layer w0.2: B1.4@5.225,91.475 B1.1@9.325,91.475 ; B1.1@9.375,91.425 9.975,91.425 10.267,91.133 10.6,91.133 10.633,91.1 v1(11.3,91.1) ; R61.2@26.1,65.867 26.133,65.867 v1(26.65,65.35) U1.7@26.65,64.55 ; v1(38.1,63.4) v1(41.5,60) ; v1(63.1,60) R5.2@63.767,60
  Top Layer w0.3: D9.1@27.275,70.5 27.875,69.9 v1(28.3,69.9)
  Routing w0.2: v1(11.3,91.1) 14.6,87.8 14.6,69.325 16.15,67.775 19.275,67.775 23,71.5 23,73.6 23.2,73.8 26.9,73.8 28.3,72.4 v1(28.3,69.9) 28.3,68.4 26.65,66.75 v1(26.65,65.35) 30.45,65.35 30.7,65.1 36.4,65.1 v1(38.1,63.4) ; v1(41.5,60) v1(63.1,60)
NetB2_2: B2.2 D10.2 U1.60 | length 43.6
  Top Layer w0.3: B2.2@15.125,64.975 15.125,67.125 v1(17,69) ; U1.60@31.65,60.55 33.75,60.55 35,61.8 35.225,61.8 D10.2@36.1,62.675 v1(37.925,64.5)
  Routing w0.2: v1(17,69) 18.7,69 20.4,70.7 20.4,73.8 21.2,74.6 26.8,74.6 32.7,68.7 36.6,68.7 37.925,67.375 v1(37.925,64.5)
NetB2_3: B2.3 R16.2 | length 1.4
  Top Layer w0.3: R16.2@9.7,64.733 9.942,64.975 B2.3@11.025,64.975
NetB3_1: B3.1 B3.4 C106.1 R74.2 U12.10 | length 25.1
  Top Layer w0.2: U12.10@61.1,91.5 60.2,91.5 57.95,89.25 57.95,84.883 56.7,83.633 56.7,80.3 57.025,79.975 C106.1@62.625,79.975 63.775,79.975 B3.4@63.8,79.95 ; B3.4@63.8,79.975 B3.4@63.8,79.95 ; B3.1@67.9,79.95 67.9,79.85 67.85,79.9 63.85,79.9 B3.4@63.8,79.95
NetBZ1_1: BZ1.1 U1.61 | length 65.3
  Top Layer w0.2: v1(8,81.7) BZ1.1@9.15,81.7
  Top Layer w0.3: v1(29.6,61.05) U1.61@31.65,61.05
  Routing w0.2: v1(8,81.7) 2.7,81.7 1.7,80.7 1.7,58.625 2.6,57.725 5.425,57.725 13.2,65.5 16.1,65.5 18.4,63.2 19.7,63.2 21.85,61.05 v1(29.6,61.05)
NetC2_3: C2.3 U1.1 | length 1.5
  Top Layer w0.4: U1.1@29.8,64.2 29.8,65.125 C2.3@30.175,65.5
NetC4_2: C4.2 L15.1 | length 0.6
  Top Layer w0.8: C4.2@35.55,23.7 L15.1@36.125,23.7
NetC5_2: C5.2 L10.2 | length 0.6
  Top Layer w0.8: C5.2@35.55,24.65 L10.2@36.125,24.65
NetC6_1: C6.1 L15.2 T3.4 | length 2
  Top Layer w0.8: L15.2@37.475,23.7 39.3,23.7 39.425,23.575
NetC7_2: C7.2 L10.1 T3.3 | length 2
  Top Layer w0.8: L10.1@37.475,24.65 39.3,24.65 39.425,24.775
NetC8_1: C8.1 FB3.2 | length 1.3
  Top Layer w0.4: C8.1@23.63,67.825 23.63,68.13 23.8,68.3 FB3.2@24.567,68.3
NetC13_1: C13.1 FB5.1 U5.11 | length 2.3
  Top Layer w0.4: U5.11@26.475,20.925 26.475,20.475 26.525,20.475 26.525,20.29 26.565,20.25 26.98,20.25 27.13,20.1 27.13,19.703 FB5.1@27.5,19.333
NetC16_1: C16.1 C105.1 R21.1 U2.2 | length 2.4
  Top Layer w0.4: C16.1@42.5,31.325 R21.1@42.5,32.9 ; R21.1@42.5,33 42.5,33.8
NetC17_2: C17.2 U3.4 | length 2.1
  Top Layer w0.24: U3.4@60.829,24.05 60.829,24.496 C17.2@62,25.667
NetC21_3: C21.3 FB2.1 | length 1
  Top Layer w0.8: 57.6,93.3 57.6,93.703 FB2.1@58.048,94.152
NetC23_1: C23.1 C96.1 U14.8
NetC24_1: C24.1 FB2.2 U12.8 | length 2.1
  Top Layer w0.8: FB2.2@59.233,94.27 60.013,94.27 60.643,94.9 U12.8@61.085,94.981
NetC30_1: C30.1 C99.3 U13.12 | length 1.7
  Top Layer w0.4: C99.3@20.7,73.2 21.5,73.2 U13.12@22.4,73.2
NetC32_1: C32.1 J9.IN | length 3.7
  Top Layer w0.4: C32.1@43.733,25.075 J9.IN@47.475,25.075
NetC32_2: C32.2 T3.1 | length 1.6
  Top Layer w0.4: T3.1@41.1,25.075 C32.2@42.667,25.075
NetC35_1: C35.1 S2.6 | length 2.1
  Top Layer w0.4: S2.6@56.2,10.641 C35.1@58.267,10.641
NetC35_2: C35.2 P5.1 | length 17.7
  Top Layer w0.4: C35.2@59.333,10.641 64.957,10.641 cw(c64.957,8.101) 66.753,9.897 68.256,8.394 cw(c66.46,6.598) 69,6.598 P5.1@69,0.682
NetC36_1: C36.1 S2.4 | length 1.3
  Top Layer w0.4: C36.1@54.277,8.877 55.175,9.775
NetC36_2: C36.2 P4.1 | length 7.6
  Top Layer w0.4: P4.1@53,0.682 53,6.861 cw(c54.785,6.861) C36.2@53.523,8.123
NetC37_1: C37.1 L11.2 T4.2 U6.1 U6.2 U7.1 U7.2 | length 9
  Top Layer w0.4: 46.575,19.325 U7.1@46.575,18.95 46.575,18.617 ccw(c48.367,18.617) C37.1@47.1,17.35 ; C37.1@46.979,17.2 48.875,17.2 48.875,16.604 ccw(c49.729,16.604) 49.125,16 ccw(c50.272,17.147) 50.272,15.525 50.639,15.525 cw(c50.639,13.989) 51.725,15.075 cw(c51.061,14.411) 52,14.411 T4.2@52,14.295
NetC37_2: C37.2 R34.1 | length 0.6
  Top Layer w0.4: R34.1@45.288,17.2 C37.2@45.912,17.2
NetC38_1: C38.1 C39.3 U9.1 U9.6 | length 5.1
  Top Layer w0.2: U9.1@12.85,74.6 v1@13.5,74.6
  Top Layer w0.6: U9.6@13,72 C38.1@14,72
  Top Layer w0.8: C38.1@14,72 C39.3@14.8,72
  Power w0.2: v1(13.4,72) 13.5,72.1 v1(13.5,74.6)
NetC40_1: C40.1 C41.1 R44.2 U9.4 | length 2.8
  Top Layer w0.3: U9.4@10.95,72 10.967,71.983 R44.2@10.967,71
  Top Layer w0.6: C40.1@9.8,72 U9.4@10.8,72
  Top Layer w0.8: 9,72 C40.1@9.8,72
NetC41_3: C41.3 J5.2 R1.2 | length 6.4
  Top Layer w1: R1.2@1,72.011 1.649,72.66 J5.2@3.3,72.66 4.951,72.66 5.6,72.011 6.9,72.011
NetC42_1: C42.1 C43.3 U10.1 U10.6 | length 5.3
  Top Layer w0.3: U10.1@33.5,43.8 v1(34.15,43.8) v1@34.2,43.8
  Top Layer w0.6: U10.6@33.65,41.2 v1(34.15,41.2) C42.1@34.65,41.2
  Top Layer w0.8: C42.1@34.65,41.2 C43.3@35.45,41.2
  Power w0.3: v1(34.15,41.2) v1(34.15,43.8) 34.15,43.9 34.2,43.85 v1@34.2,43.8
NetC44_1: C44.1 C45.1 R28.2 U10.4 | length 2.5
  Top Layer w0.33: R28.2@31.6,40.501 U10.4@31.6,41.2
  Top Layer w0.6: C44.1@30.45,41.2 U10.4@31.45,41.2
  Top Layer w0.8: 29.65,41.2 C44.1@30.45,41.2
NetC45_3: C45.3 J20.2 R2.2 | length 2.6
  Top Layer w0.8: J20.2@33.915,48.05 34.464,48.599 R2.2@34.464,50.4
  other v1: 34.25,46.925 33.325,47 34.3,49.1
  other v6: 27.4,42.025
  other v7: 27.4,40.375 27.4,41.2
NetC46_1: C46.1 C47.3 U11.6 | length 1.8
  Top Layer w0.6: C46.1@54.6,42.2 U11.6@55.6,42.2
  Top Layer w0.8: C47.3@53.8,42.2 C46.1@54.6,42.2
NetC48_1: C48.1 C49.1 R30.2 U11.4 | length 3
  Top Layer w0.3: U11.4@57.65,42.2 57.8,42.2 57.687,42.313 R30.2@57.687,43.2
  Top Layer w0.6: U11.4@57.8,42.2 C48.1@58.8,42.2
  Top Layer w0.8: C48.1@58.8,42.2 59.6,42.2
NetC49_3: C49.3 J21.2 R3.2 | length 2.1
  Top Layer w1.5: J21.2@72.725,44.11 74.401,44.11 R3.2@74.706,43.806
  other v6: 61.85,41.375 62.675,41.375 62.675,42.2 62.675,43.025 73.55,43.225 71.65,43.325 71.85,45.1 73.4,45.125
  other v7: 61.85,42.2 61.85,43.025
NetC51_1: C51.1 U4.3 | length 1
  Top Layer w0.3: U4.3@21.915,32.154 C51.1@22.867,32.154
NetC91_1: C91.1 FB1.2 FB5.2 | length 7
  Top Layer w0.4: FB1.2@30.033,22.03 v6(30.47,22.03)
  Top Layer w0.5: FB5.2@27.5,18.267 FB5.2@27.508,18.267
  Top Layer w0.8: v6(27.6,17.9) 27.6,18.1 27.638,18.137 v6@27.888,17.888
  Power w0.8: v6(27.6,17.9) 27.9,18.2 27.9,20.5 29.43,22.03 v6(30.47,22.03)
NetC96_3: C96.3 FB7.1
NetC97_1: C97.1 C98.1 D21.1 FB7.2 P2.2 | length 11.9
  Top Layer w0.4: D21.1@33.74,83.809 P2.2@33.74,85.2
  Top Layer w1.5: P2.2@33.74,85.2 34.64,86.1 38.5,86.1 39.85,84.75 FB7.2@39.85,81.275
NetC97_2: C97.2 R86.2 | length 0.8
  Top Layer w0.8: C97.2@41.625,84 R86.2@42.4,84
NetC100_1: C100.1 P1.6 | length 8.9
  Top Layer w0.8: C100.1@18.2,94.133 18.517,94.45 P1.6@20.399,94.45 ; P1.6@20.399,94.4 P1.6@20.7,94.4 P1.6@22.7,94.4 P1.6@24.7,94.4 P1.6@26.7,94.4 P1.6@27.001,94.4
NetC100_2: C100.2 R89.1 | length 1.1
  Top Layer w0.8: R89.1@18.2,91.633 C100.2@18.2,92.767
NetC104_3: C104.3 R10.2 R20.2 | length 1.7
  Top Layer w0.4: R20.2@42.3,39.933 R10.2@43.2,39.933 43.367,40.1 43.4,40.1 43.4,40.325 C104.3@43.625,40.55
NetC107_1: C107.1 J9.OUT | length 2.2
  Top Layer w0.4: J9.OUT@50.25,25.075 C107.1@52.446,25.075
NetC107_2: C107.2 S1.6 | length 1.8
  Top Layer w0.4: C107.2@53.354,25.075 S1.6@55.2,25.075
NetC108_1: C108.1 S1.4 | length 2.1
  Top Layer w0.39: S1.4@56.2,25.075 C108.1@56.2,27.146
NetC108_2: C108.2 J6.OUT | length 1.5
  Top Layer w0.4: C108.2@56.2,28.054 J6.OUT@56.2,29.55
NetC109_1: C109.1 S1.2 | length 0.6
  Top Layer w0.4: C109.1@55.7,23.004 S1.2@55.7,23.625
NetC110_1: C110.1 R55.1 X3.3 | length 7.6
  Top Layer w0.2: X3.3@24.095,36.854 25.028,36.854 C110.1@25.695,36.187 26.3,35.582 26.3,34.1 24.975,32.775 R55.1@24.975,31.233
NetC111_1: C111.1 R54.2 X3.1 | length 6.1
  Top Layer w0.2: X3.1@21.895,35.254 20.428,35.254 C111.1@20.295,35.12 20.295,34.5 20.862,33.933 R54.2@23.9,33.933
NetC112_1: C112.1 S2.2 | length 0.9
  Top Layer w0.4: C112.1@54.046,11.929 S2.2@54.662,11.313
NetC112_2: C112.2 T4.6 | length 0.9
  Top Layer w0.4: T4.6@52.733,13.233 53.369,12.596 C112.2@53.379,12.596
NetD14_2: D14.2 R77.2 | length 1.6
  Top Layer w0.3: R77.2@72.712,82.267 72.74,82.295 D14.2@74.275,82.295
NetD15_2: D15.2 R81.2 | length 0.7
  Top Layer w0.3: D15.2@33.82,63.4 34.467,63.4 R81.2@34.5,63.433
NetD28_1: D28.1 P3.2 R19.1 | length 4.8
  Top Layer w0.2: R19.1@64.833,59 66.4,59 66.533,58.867 P3.2@69.55,58.867 P3.2@69.565,58.867
NetD29_1: D29.1 P3.4 R42.1 | length 5.3
  Top Layer w0.2: R42.1@64.833,57 66.3,57 66.6,57.3 68.593,57.3 P3.4@69.565,56.327
NetD30_1: D30.1 P3.6 R46.1 | length 9.4
  Top Layer w0.2: R46.1@64.833,56 65.494,56 D30.1@65.5,55.993 65.9,55.593 65.9,55.2 68.5,52.6 69.6,52.6 70.2,53.2 70.2,54.422 P3.6@70.835,55.057
NetD31_1: D31.1 P3.8 R4.1 | length 6.3
  Top Layer w0.2: R4.1@64.833,58 66.3,58 66.5,58.2 70.233,58.2 P3.8@70.835,57.597
NetD32_1: D32.1 P3.10 R5.1 | length 6.5
  Top Layer w0.2: R5.1@64.833,60 66.4,60 66.9,59.5 70.198,59.5 P3.10@70.835,60.137
NetFB4_2: FB4.2 U4.4 | length 1
  Top Layer w0.4: U4.4@18.885,32.154 18.9,32.169 FB4.2@18.9,33.167
NetJ1_IN: J1.IN T5.1 | length 1.2
  Top Layer w0.4: 32.625,31.925 32.925,32.225 J1.IN@33.505,32.805
NetJ1_OUT: J1.OUT U2.13 | length 7.9
  Top Layer w0.4: J1.OUT@35.095,34.395 37.376,36.676 cw(c39.172,34.88) 39.172,37.42 U2.13@41.9,37.42
NetJ3_IN: J3.IN T4.5 | length 2.7
  Top Layer w0.4: J3.IN@50.25,11.095 51.795,12.64 ; 51.795,12.64 ccw(c51.3,13.135) 52,13.135
NetJ3_OUT: J3.OUT T6.1 | length 1.1
  Top Layer w0.4: 46.425,11.095 J3.OUT@47.475,11.095
NetJ19_1: J19.1 R78.2 U1.62 U12.9 | length 78.4
  Top Layer w0.2: v19(37.55,61.625) 38.875,60.3 v19(39.317,60.3) ; v1(60,92.9) U12.9@61.1,92.9 ; R78.2@71.033,74.5 72.725,76.192 J19.1@72.725,76.4
  Top Layer w0.3: U1.62@31.65,61.55 32.4,61.55 v1(32.725,61.225)
  Routing w0.2: v1(32.725,61.225) 32.75,61.2 33.7,61.2 34.5,62 35.55,62 35.925,61.625 v19(37.55,61.625) ; v19(39.317,60.3) 39.317,60.517 53.975,75.175 71.5,75.175 J19.1@72.725,76.4 71.3,77.825 71.3,81.4 67.7,85 61,85 60.65,85.35 60.65,92.25 v1(60,92.9)
NetL12_2: L12.2 R26.2 R34.2 R35.2 U7.8 U7.9 U8.1 U8.2 | length 7.4
  Top Layer w0.4: 38.95,17.2 R34.2@44.221,17.2 ; R34.2@44.1,17.35 ccw(c42.833,18.617) 44.625,18.617 44.625,19.325
NetP1_1: P1.1 U14.1
NetP1_5: P1.5 U14.4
